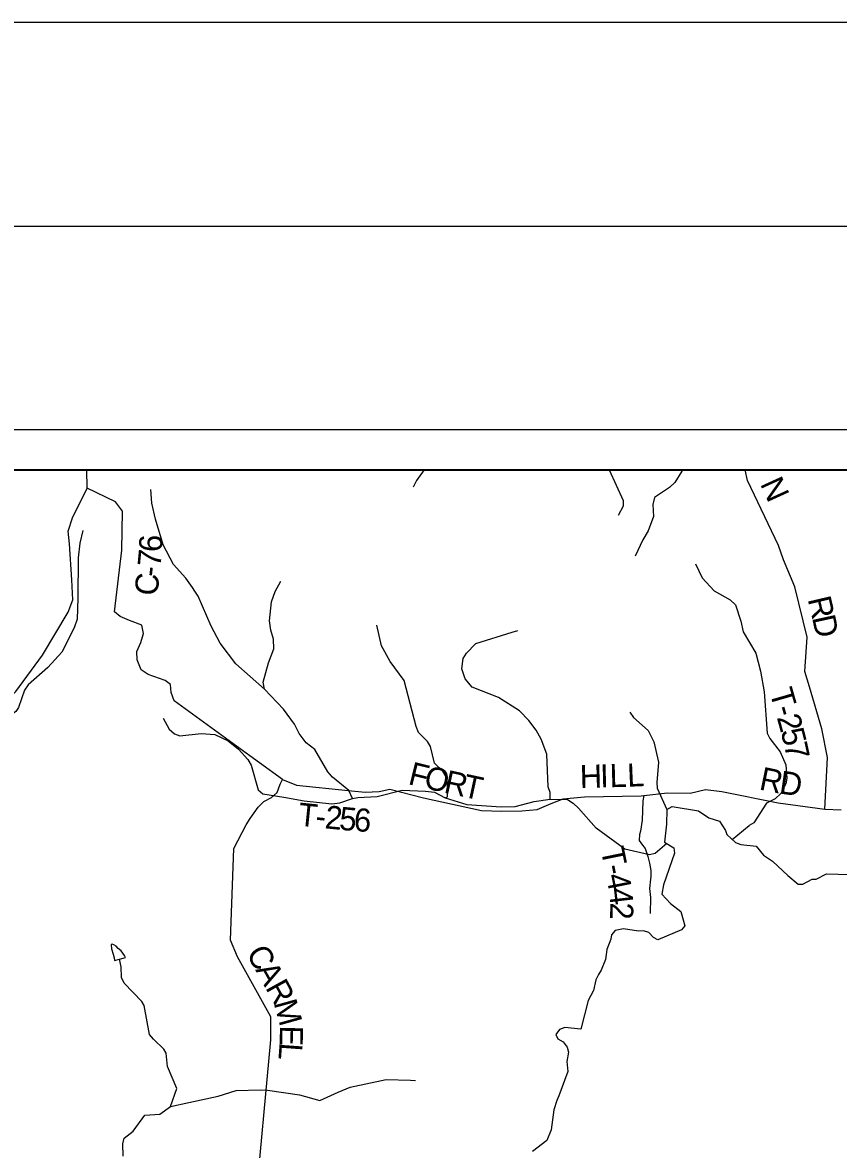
# Model space of a CAD drawing. Extents: x 0 to 34, y 0 to 22.
# Drawn here: x 3.854 to 5.858, y 19.231 to 22 of the extents above; entities that cross this region are included whole.
import ezdxf

# ---------------------------------------------------------------- set-up
doc = ezdxf.new("R2010")
doc.units = 0
for name, color, linetype in [('GM_X_County', 7, 'Continuous'), ('GM_X_County_Road', 7, 'Continuous'), ('GM_X_County_Road_Text', 7, 'Continuous'), ('GM_X_Major_River', 7, 'Continuous'), ('GM_X_Minor_Lake', 7, 'Continuous'), ('GM_X_Minor_River', 7, 'Continuous'), ('GM_X_Township_Road', 7, 'Continuous'), ('GM_X_Township_Road_Text', 7, 'Continuous'), ('SH_Border', 7, 'Continuous'), ('SH_Cut_Line', 7, 'Continuous'), ('SH_Data', 7, 'Continuous')]:
    doc.layers.add(name, color=color, linetype=linetype)

msp = doc.modelspace()

# ---------------------------------------------------------------- linework, layer by layer
at = {"layer": 'GM_X_County'}
msp.add_lwpolyline([(7.6111, 20.9006), (2.6, 20.9006), (2.6, 14.46)], dxfattribs=at)
at = {"layer": 'GM_X_County_Road'}
msp.add_lwpolyline([(4.4248, 19.0839), (4.4636, 19.5004), (4.4639, 19.5567), (4.3817, 19.7044), (4.3645, 19.7452), (4.3726, 19.9705), (4.4034, 20.0289), (4.4129, 20.0443), (4.4329, 20.0719), (4.4461, 20.0861), (4.4657, 20.0962), (4.4789, 20.1077), (4.4866, 20.1284), (4.4926, 20.1401), (4.3796, 20.2222), (4.2263, 20.333), (4.2192, 20.3537), (4.217, 20.3731), (4.204, 20.3833), (4.1626, 20.3983), (4.1451, 20.4098), (4.1354, 20.434), (4.1344, 20.4549), (4.144, 20.4767), (4.151, 20.4986), (4.1469, 20.5196), (4.1168, 20.5309), (4.0939, 20.5402), (4.0794, 20.5523), (4.0978, 20.7032), (4.0993, 20.7993), (4.0821, 20.8221), (4.0123, 20.8557), (4.0119, 20.9006)], dxfattribs=at)
at = {"layer": 'GM_X_Major_River'}
for points in [[(5.4367, 20.0663), (5.4356, 20.0299)], [(5.4367, 20.0663), (5.4495, 20.0735), (5.5144, 20.0627), (5.5399, 20.0462), (5.5664, 20.0374), (5.5806, 20.0146)], [(5.4356, 20.0299), (5.4309, 19.9861), (5.4534, 19.9722), (5.4552, 19.9593), (5.4287, 19.8815), (5.4243, 19.8584), (5.446, 19.8351), (5.4708, 19.8159), (5.481, 19.7805), (5.4726, 19.7704), (5.4149, 19.7459), (5.4036, 19.7521), (5.3927, 19.7644), (5.3795, 19.7683), (5.3666, 19.7673), (5.3304, 19.7729), (5.3099, 19.769), (5.3003, 19.7581), (5.2991, 19.7475), (5.2894, 19.7222), (5.2861, 19.6979), (5.2749, 19.6715), (5.2687, 19.6613), (5.2625, 19.6481), (5.2562, 19.6213), (5.2435, 19.5968), (5.2254, 19.5268), (5.1861, 19.531), (5.1732, 19.5254), (5.164, 19.5134), (5.1688, 19.5031), (5.1823, 19.4954), (5.192, 19.482), (5.1949, 19.4699), (5.1913, 19.4475), (5.1937, 19.4229), (5.1712, 19.3625), (5.1665, 19.3511), (5.1591, 19.3285), (5.1522, 19.2789), (5.1417, 19.2532), (5.1063, 19.2259)], [(5.5806, 20.0146), (5.5839, 20.0051), (5.6053, 19.9855), (5.6185, 19.9801), (5.6563, 19.9763), (5.6738, 19.9538), (5.696, 19.9395), (5.7342, 19.9039), (5.7594, 19.8832), (5.7707, 19.8827), (5.7936, 19.8953), (5.8034, 19.8952), (5.8289, 19.9079), (5.9151, 19.9059)]]:
    msp.add_lwpolyline(points, dxfattribs=at)
at = {"layer": 'GM_X_Minor_Lake'}
for points in [[(4.0917, 19.6987), (4.1065, 19.7028), (4.1043, 19.7077), (4.0957, 19.7192), (4.0886, 19.7249), (4.0833, 19.7303), (4.0781, 19.7341), (4.0739, 19.7353), (4.0716, 19.7334), (4.0723, 19.7236), (4.0763, 19.711), (4.0785, 19.7015), (4.0796, 19.6954)], [(4.0796, 19.6954), (4.0917, 19.6987)]]:
    msp.add_lwpolyline(points, dxfattribs=at)
at = {"layer": 'GM_X_Minor_River'}
for points in [[(4.8401, 20.9006), (4.8216, 20.8749), (4.8137, 20.8587)], [(5.2946, 20.9006), (5.3294, 20.8259), (5.3296, 20.8114), (5.3174, 20.7889)], [(5.4775, 20.9006), (5.4732, 20.8974), (5.4559, 20.8696), (5.4432, 20.8576), (5.4067, 20.8328), (5.4025, 20.8154), (5.4035, 20.7862), (5.3907, 20.7507), (5.3774, 20.7289), (5.3591, 20.6886)], [(4.6645, 20.0932), (4.6557, 20.1131), (4.6153, 20.1457), (4.6038, 20.1585), (4.5714, 20.2134), (4.5501, 20.2301), (4.5331, 20.2532), (4.5217, 20.2758), (4.4951, 20.3132), (4.4478, 20.3623), (4.378, 20.4243), (4.3391, 20.4752), (4.3174, 20.517), (4.285, 20.5909), (4.2773, 20.6024), (4.2714, 20.612), (4.2547, 20.6351), (4.2246, 20.6687), (4.1993, 20.717), (4.1804, 20.78), (4.1713, 20.8193), (4.1685, 20.8525)], [(4.0014, 20.7517), (3.9944, 20.7211), (3.9907, 20.6847), (3.9892, 20.5855), (3.9875, 20.5343), (3.9806, 20.5123), (3.9499, 20.4529), (3.9157, 20.4151), (3.8675, 20.373), (3.8581, 20.3595), (3.844, 20.3168), (3.837, 20.3071), (3.8004, 20.2789), (3.7897, 20.257), (3.7756, 20.2307), (3.7366, 20.1957), (3.7009, 20.118), (3.6888, 20.0795), (3.6776, 20.0694), (3.6677, 20.0677), (3.6413, 20.0735), (3.6293, 20.0631), (3.6211, 20.0503), (3.617, 20.0375)], [(5.5069, 20.6696), (5.5237, 20.6358), (5.5527, 20.6038), (5.5925, 20.5814), (5.6052, 20.5694), (5.6181, 20.5293), (5.6245, 20.5025), (5.6554, 20.4503), (5.6671, 20.4064), (5.6756, 20.3557), (5.6832, 20.2538), (5.6898, 20.2407), (5.715, 20.208), (5.7292, 20.1762), (5.7312, 20.1435), (5.7291, 20.1291), (5.7169, 20.1054), (5.7026, 20.0927), (5.6815, 20.0821), (5.6506, 20.0332), (5.6387, 20.027)], [(4.4478, 20.3623), (4.4451, 20.379), (4.4577, 20.4267), (4.4713, 20.461), (4.4706, 20.4849), (4.4638, 20.5071), (4.4608, 20.53), (4.4655, 20.5762), (4.4747, 20.6019), (4.4885, 20.6271)], [(4.8919, 20.0948), (4.8977, 20.0973), (4.898, 20.1327), (4.8944, 20.1464), (4.886, 20.1606), (4.8655, 20.1804), (4.8563, 20.2208), (4.8486, 20.2331), (4.8266, 20.2559), (4.8204, 20.2704), (4.7911, 20.3831), (4.757, 20.4296), (4.7357, 20.4688), (4.7238, 20.5191)], [(5.1501, 20.092), (5.15, 20.1084), (5.145, 20.1221), (5.1419, 20.202), (5.1278, 20.2391), (5.1153, 20.261), (5.0979, 20.2848), (5.0744, 20.3088), (5.023, 20.3416), (4.9582, 20.3671), (4.9415, 20.3876), (4.9328, 20.4117), (4.9364, 20.4371), (4.9442, 20.4506), (4.9674, 20.4741), (5.0568, 20.5018), (5.0702, 20.5061)], [(5.3455, 20.3051), (5.3543, 20.2924), (5.3906, 20.2602), (5.4045, 20.2322), (5.4164, 20.1826), (5.4117, 20.1325), (5.413, 20.1184), (5.4367, 20.0664)], [(4.1989, 20.2907), (4.214, 20.2635), (4.2266, 20.2519), (4.2402, 20.2471), (4.2924, 20.2533), (4.3265, 20.2505), (4.3588, 20.2351), (4.3846, 20.2145), (4.4069, 20.189), (4.415, 20.1752), (4.4325, 20.1144), (4.4441, 20.1047), (4.4956, 20.097), (4.5459, 20.0873), (4.6134, 20.0804), (4.6328, 20.0831), (4.6645, 20.0932), (4.6774, 20.096), (4.7253, 20.0985), (4.7867, 20.1138), (4.844, 20.1112), (4.866, 20.1089), (4.8919, 20.0948), (4.9456, 20.079), (5.0294, 20.0725), (5.0639, 20.0738), (5.1109, 20.0863), (5.1501, 20.092), (5.1926, 20.0909), (5.2068, 20.0815), (5.2195, 20.0699), (5.2626, 20.0205)], [(5.4364, 19.9827), (5.4083, 19.9583), (5.3942, 19.955), (5.3331, 19.9685), (5.2626, 20.0205)], [(5.5973, 19.9929), (5.6387, 20.027)], [(4.2171, 19.3363), (4.2331, 19.3808), (4.2094, 19.4345), (4.2063, 19.4679), (4.2011, 19.4778), (4.1756, 19.5019), (4.1656, 19.5138), (4.1526, 19.5848), (4.1471, 19.5947), (4.1032, 19.6395), (4.097, 19.6532), (4.0957, 19.6801), (4.0922, 19.6989)], [(4.1005, 19.2142), (4.0997, 19.2449), (4.1036, 19.2589), (4.1257, 19.2757), (4.1545, 19.3149), (4.1912, 19.3179), (4.2171, 19.3363), (4.2619, 19.3464), (4.3343, 19.362), (4.3787, 19.3756), (4.4385, 19.3777), (4.4551, 19.3767), (4.5341, 19.365), (4.5839, 19.3516), (4.6291, 19.3716), (4.6584, 19.3838), (4.7471, 19.4027), (4.8065, 19.4009), (4.8189, 19.4008)]]:
    msp.add_lwpolyline(points, dxfattribs=at)
at = {"layer": 'GM_X_Township_Road'}
for points in [[(5.8251, 20.0674), (5.8312, 20.1942), (5.8177, 20.2648), (5.7875, 20.3677), (5.7755, 20.4057), (5.7817, 20.4899), (5.7513, 20.6137), (5.7233, 20.6794), (5.7112, 20.715), (5.635, 20.8749), (5.6289, 20.9006)], [(3.5141, 19.7748), (3.589, 19.8343), (3.6004, 19.8443), (3.6087, 19.8917), (3.6657, 20.0244), (3.6626, 20.0636), (3.6716, 20.0892), (3.6899, 20.1268), (3.7309, 20.2223), (3.7585, 20.2661), (3.8035, 20.3228), (3.8369, 20.3559), (3.9027, 20.4452), (3.9656, 20.5516), (3.9773, 20.5817), (3.9747, 20.6308), (3.9688, 20.7188), (3.9658, 20.75), (3.976, 20.7828), (4.0123, 20.8557)], [(4.4926, 20.1401), (4.5271, 20.1259), (4.6535, 20.1127), (4.6952, 20.1087), (4.7297, 20.1109), (4.756, 20.1163), (4.839, 20.0954), (4.9809, 20.0642), (5.0309, 20.0623), (5.0807, 20.063), (5.1183, 20.0663), (5.1524, 20.0807), (5.1823, 20.0925), (5.234, 20.0974), (5.3733, 20.1002), (5.3797, 20.1009), (5.438, 20.1074), (5.4941, 20.1068), (5.5315, 20.1154), (5.5716, 20.1106), (5.7105, 20.0823), (5.8251, 20.0674), (5.8649, 20.0653)], [(5.3797, 20.1009), (5.378, 20.0878), (5.3768, 20.0639), (5.3764, 20.04), (5.3722, 20.013), (5.3691, 20.0047), (5.3687, 19.9899), (5.374, 19.9822), (5.3831, 19.9708), (5.3902, 19.9507), (5.394, 19.9343), (5.397, 19.9168), (5.397, 19.9016), (5.3964, 19.8958)], [(5.3964, 19.8958), (5.3964, 19.8953), (5.3943, 19.872), (5.3965, 19.8503), (5.3953, 19.8108)]]:
    msp.add_lwpolyline(points, dxfattribs=at)
at = {"layer": 'SH_Border'}
msp.add_lwpolyline([(2, 21.5), (33.5, 21.5), (33.5, 0.5), (2, 0.5)], close=True, dxfattribs=at)
at = {"layer": 'SH_Cut_Line'}
msp.add_lwpolyline([(0, 0), (34, 0), (34, 22), (0, 22)], close=True, dxfattribs=at)
at = {"layer": 'SH_Data'}
for p, q in [((2.5, 21), (9.5, 21)), ((2.6, 20.9), (9.4, 20.9))]:
    msp.add_line(p, q, dxfattribs=at)

# ---------------------------------------------------------------- texts
at = {"layer": 'GM_X_County_Road_Text'}
for s, rotation, p in [('6', 87.2931, (4.1959, 20.698)), ('7', 84.6729, (4.1925, 20.6604)), ('-', 83.7955, (4.1899, 20.6362)), ('C', 83.5387, (4.1846, 20.5896)), ('C', 298.8207, (4.4021, 19.7136)), ('A', 299.2194, (4.4248, 19.6724)), ('R', 298.7893, (4.4492, 19.6288)), ('M', 285.558, (4.4703, 19.5911)), ('E', 268.6971, (4.4863, 19.5361)), ('L', 265.8738, (4.4854, 19.4944))]:
    msp.add_text(s, height=0.0568, rotation=rotation, dxfattribs=at).set_placement(p)
at = {"layer": 'GM_X_Township_Road_Text'}
for s, rotation, p in [('N', 294.5337, (5.665, 20.8667)), ('R', 283.2591, (5.7824, 20.5834)), ('D', 282.2044, (5.7931, 20.5382)), ('T', 286.0884, (5.6884, 20.3559)), ('2', 285.3692, (5.7065, 20.2928)), ('-', 285.9261, (5.7002, 20.3151)), ('5', 284.2546, (5.7157, 20.2593)), ('7', 282.0682, (5.7242, 20.226)), ('F', 345.996, (4.7987, 20.1291)), ('O', 347.2641, (4.8373, 20.1195)), ('R', 347.7674, (4.8866, 20.1083)), ('H', 1.5338, (5.2234, 20.1189)), ('I', 1.5302, (5.2734, 20.1202)), ('L', 1.5548, (5.2967, 20.1209)), ('L', 2.4434, (5.3402, 20.1221)), ('R', 348.4275, (5.6613, 20.1159)), ('D', 352.005, (5.7108, 20.1059)), ('T', 347.7766, (4.9322, 20.0984)), ('T', 354.2173, (4.5291, 20.0269)), ('2', 354.3632, (4.5948, 20.0202)), ('5', 354.8114, (4.6301, 20.0168)), ('6', 356.1873, (4.6664, 20.0135)), ('-', 354.2572, (4.5715, 20.0226)), ('T', 281.3847, (5.274, 19.9688)), ('-', 281.3696, (5.2824, 19.9271)), ('4', 281.2293, (5.287, 19.9043)), ('4', 276.6764, (5.2936, 19.8711)), ('2', 269.4432, (5.2976, 19.8382))]:
    msp.add_text(s, height=0.0568, rotation=rotation, dxfattribs=at).set_placement(p)

doc.saveas('drawing.dxf')
